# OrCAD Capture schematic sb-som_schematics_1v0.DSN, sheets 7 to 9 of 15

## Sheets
7 05. Parallel Display Interface: size C; title: SB-SOM    05. Parallel Display Interface
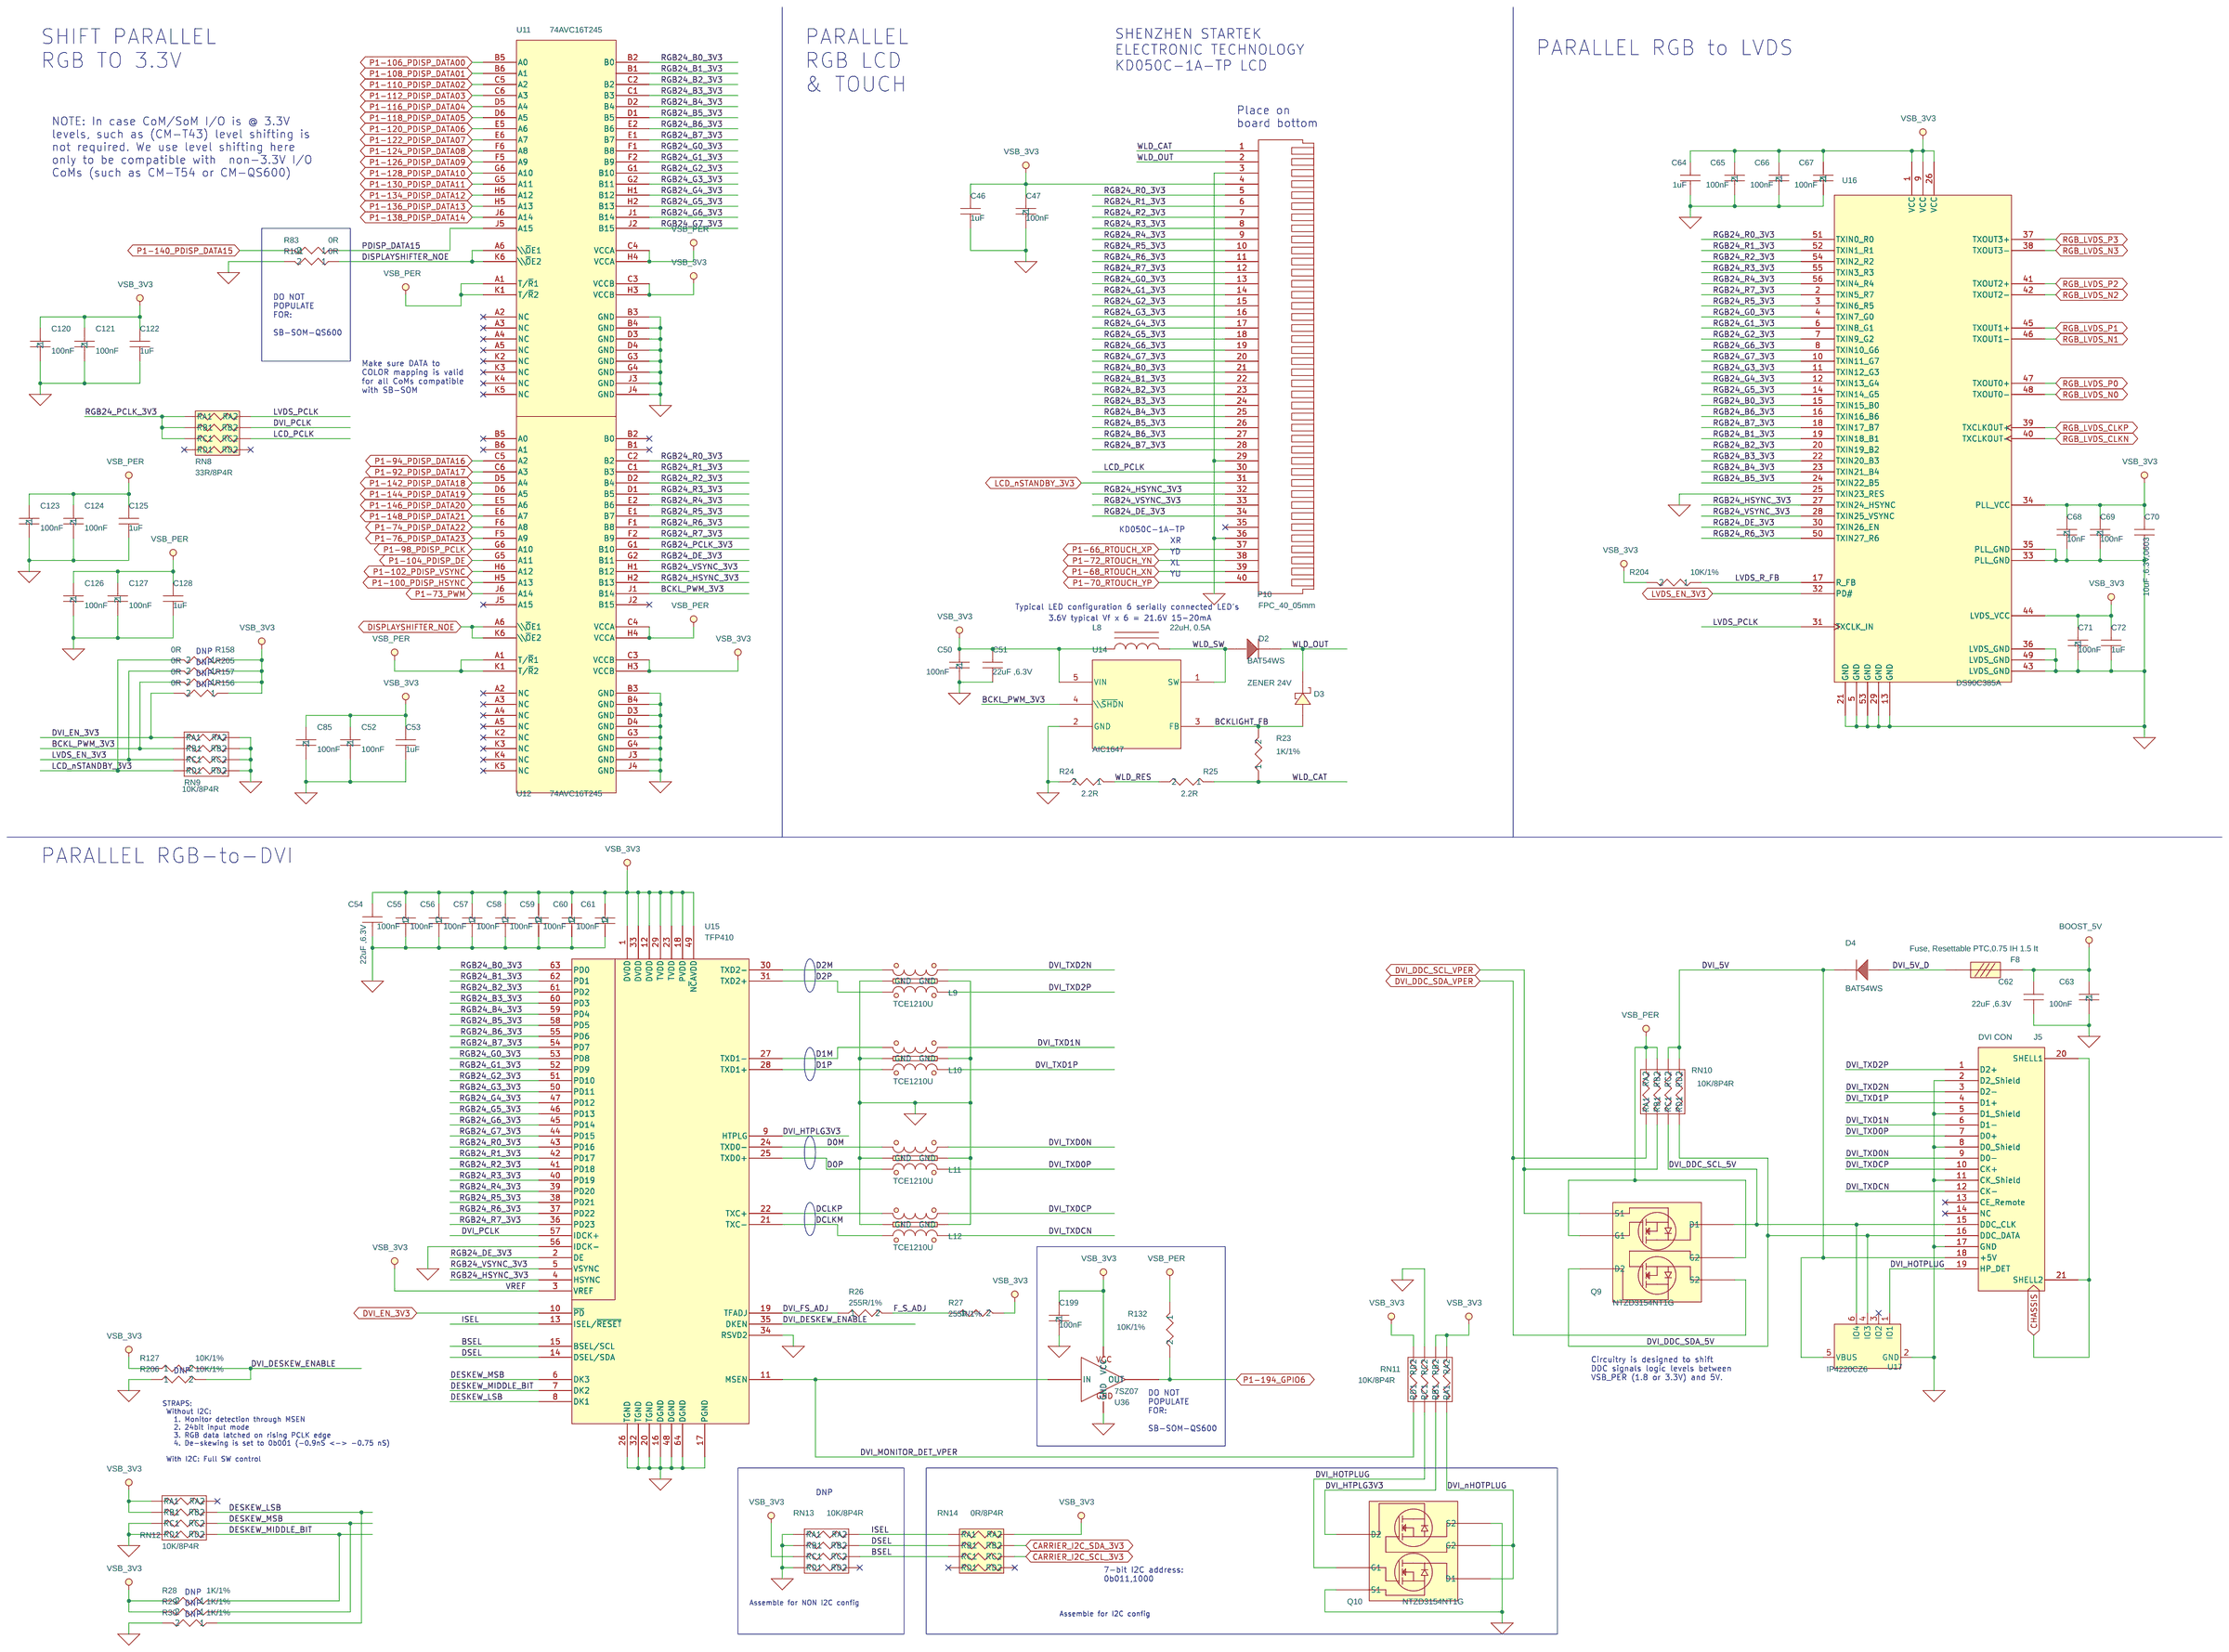
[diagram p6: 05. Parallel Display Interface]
8 07. PCIE & SATA: size C; title: SB-SOM    07. PCIE & SATA
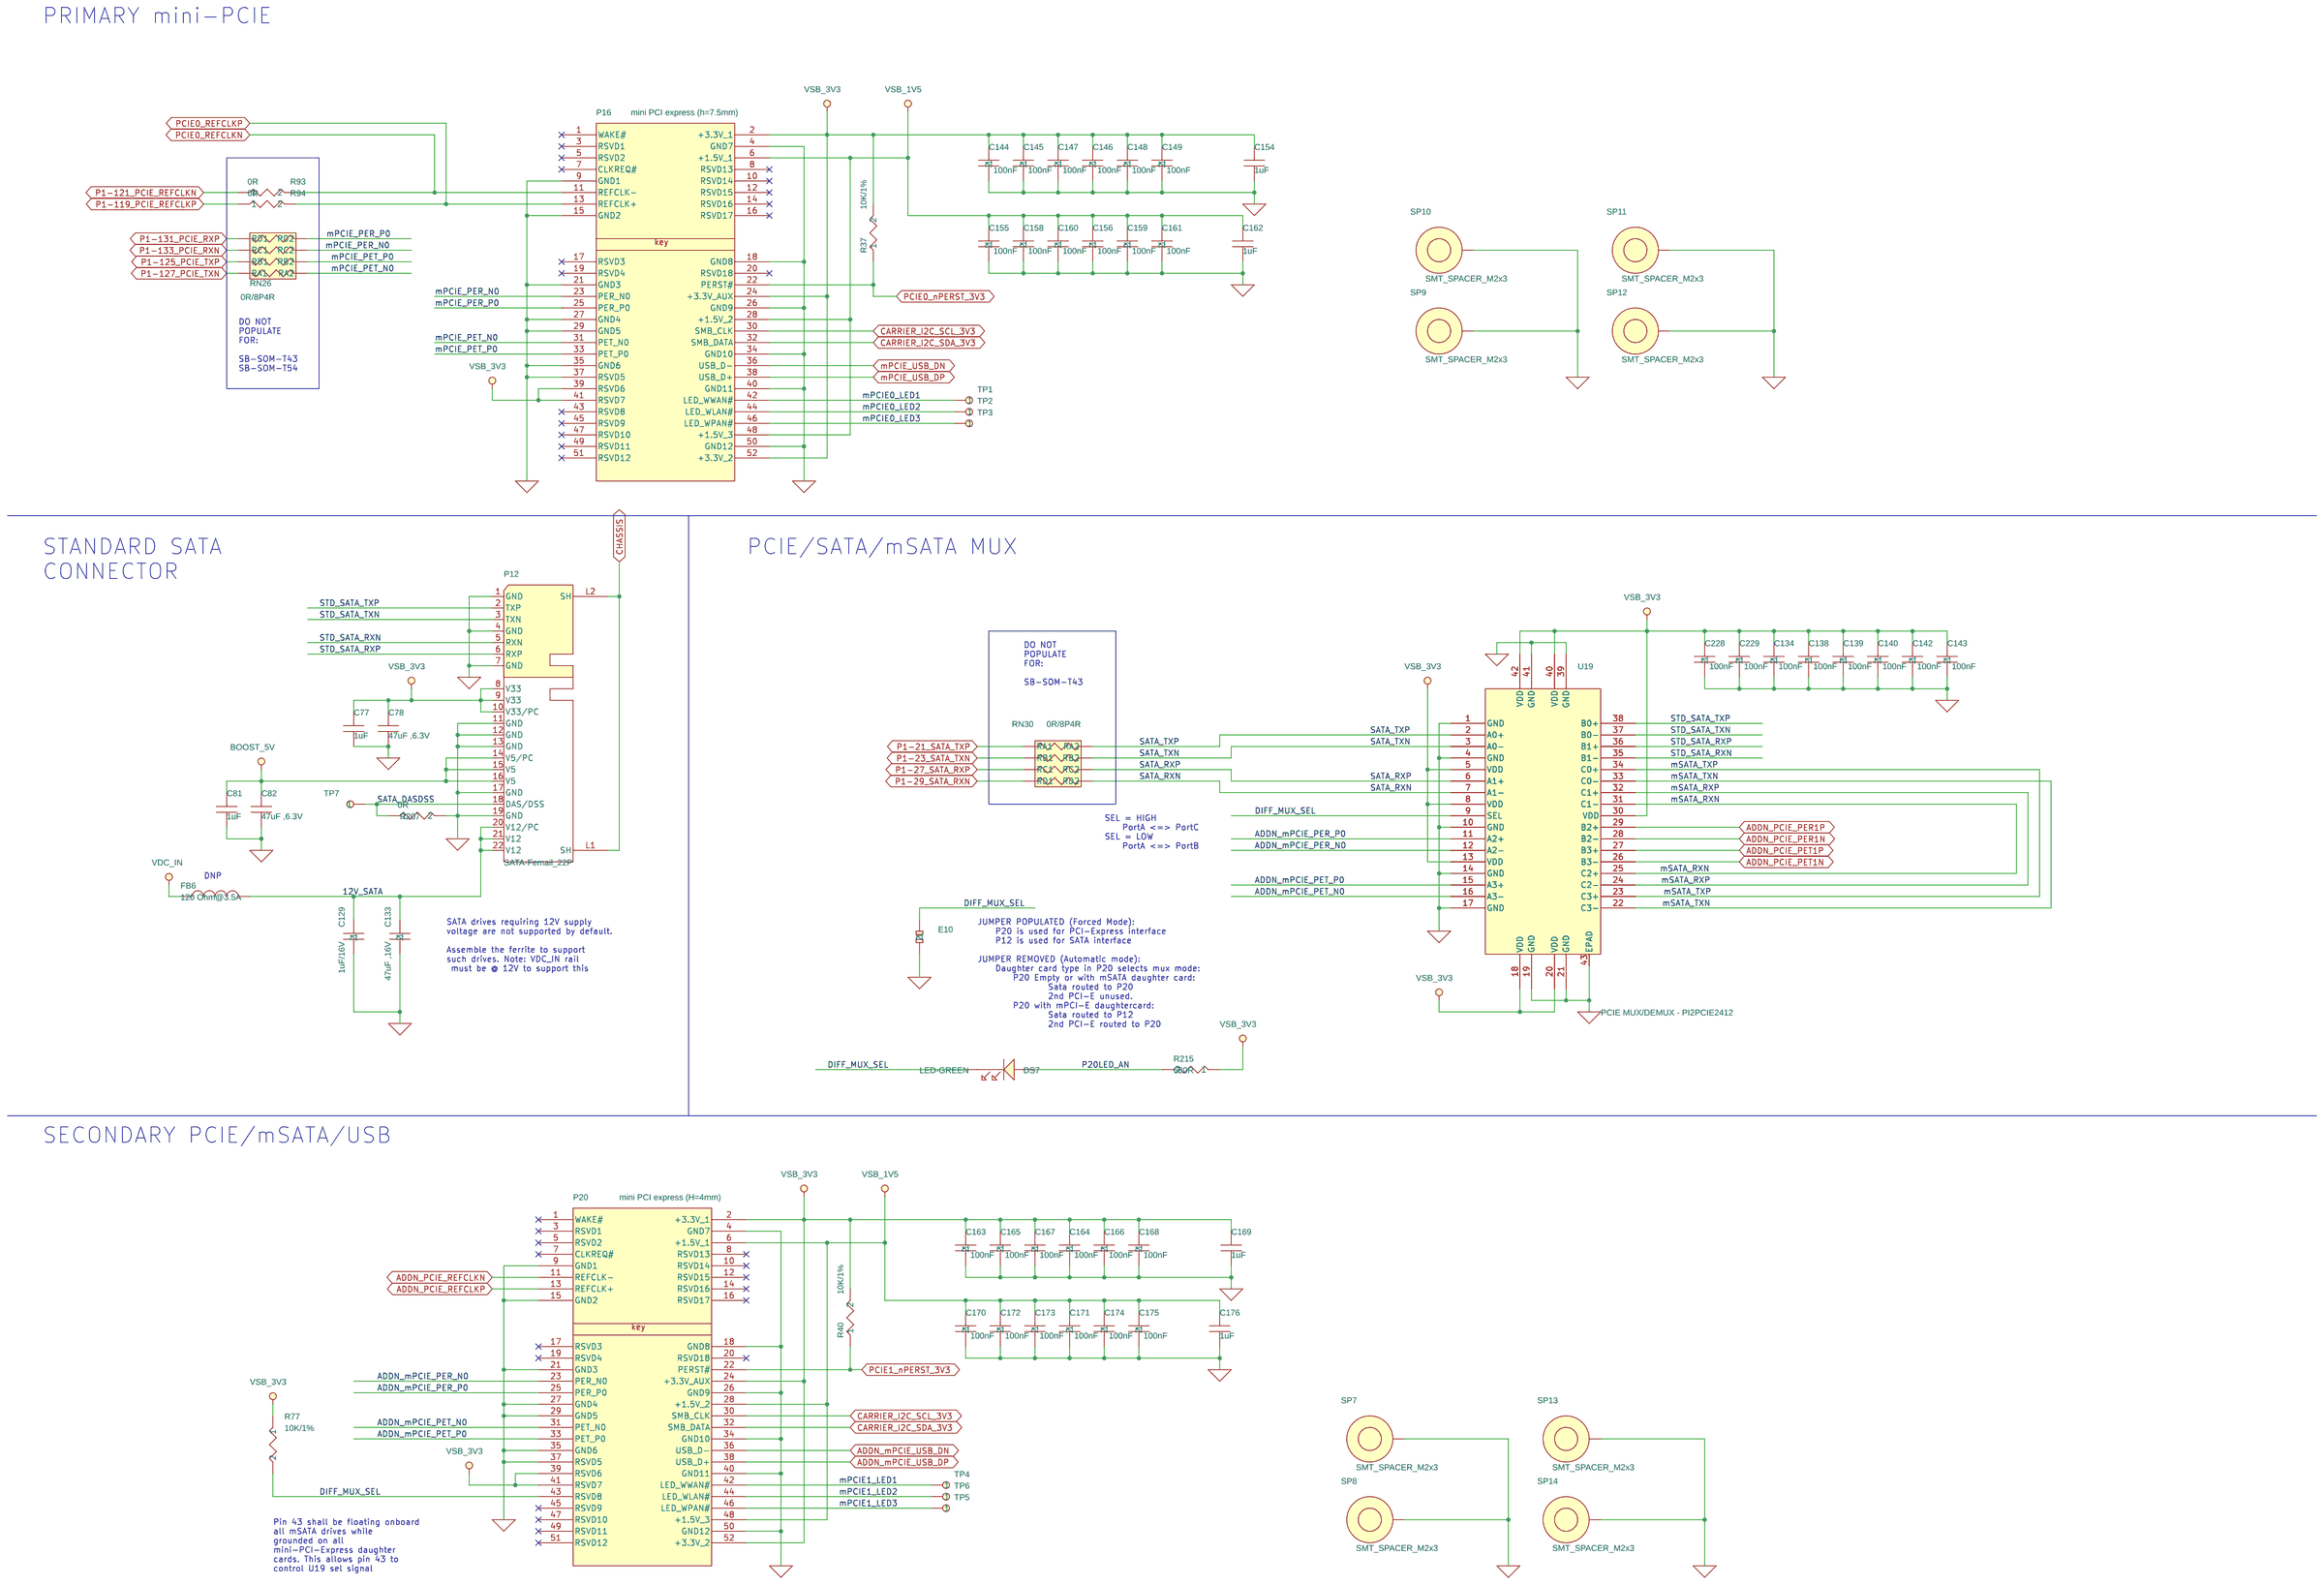
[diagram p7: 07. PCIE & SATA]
9 10. Power: size C; title: SB-SOM    10. Power
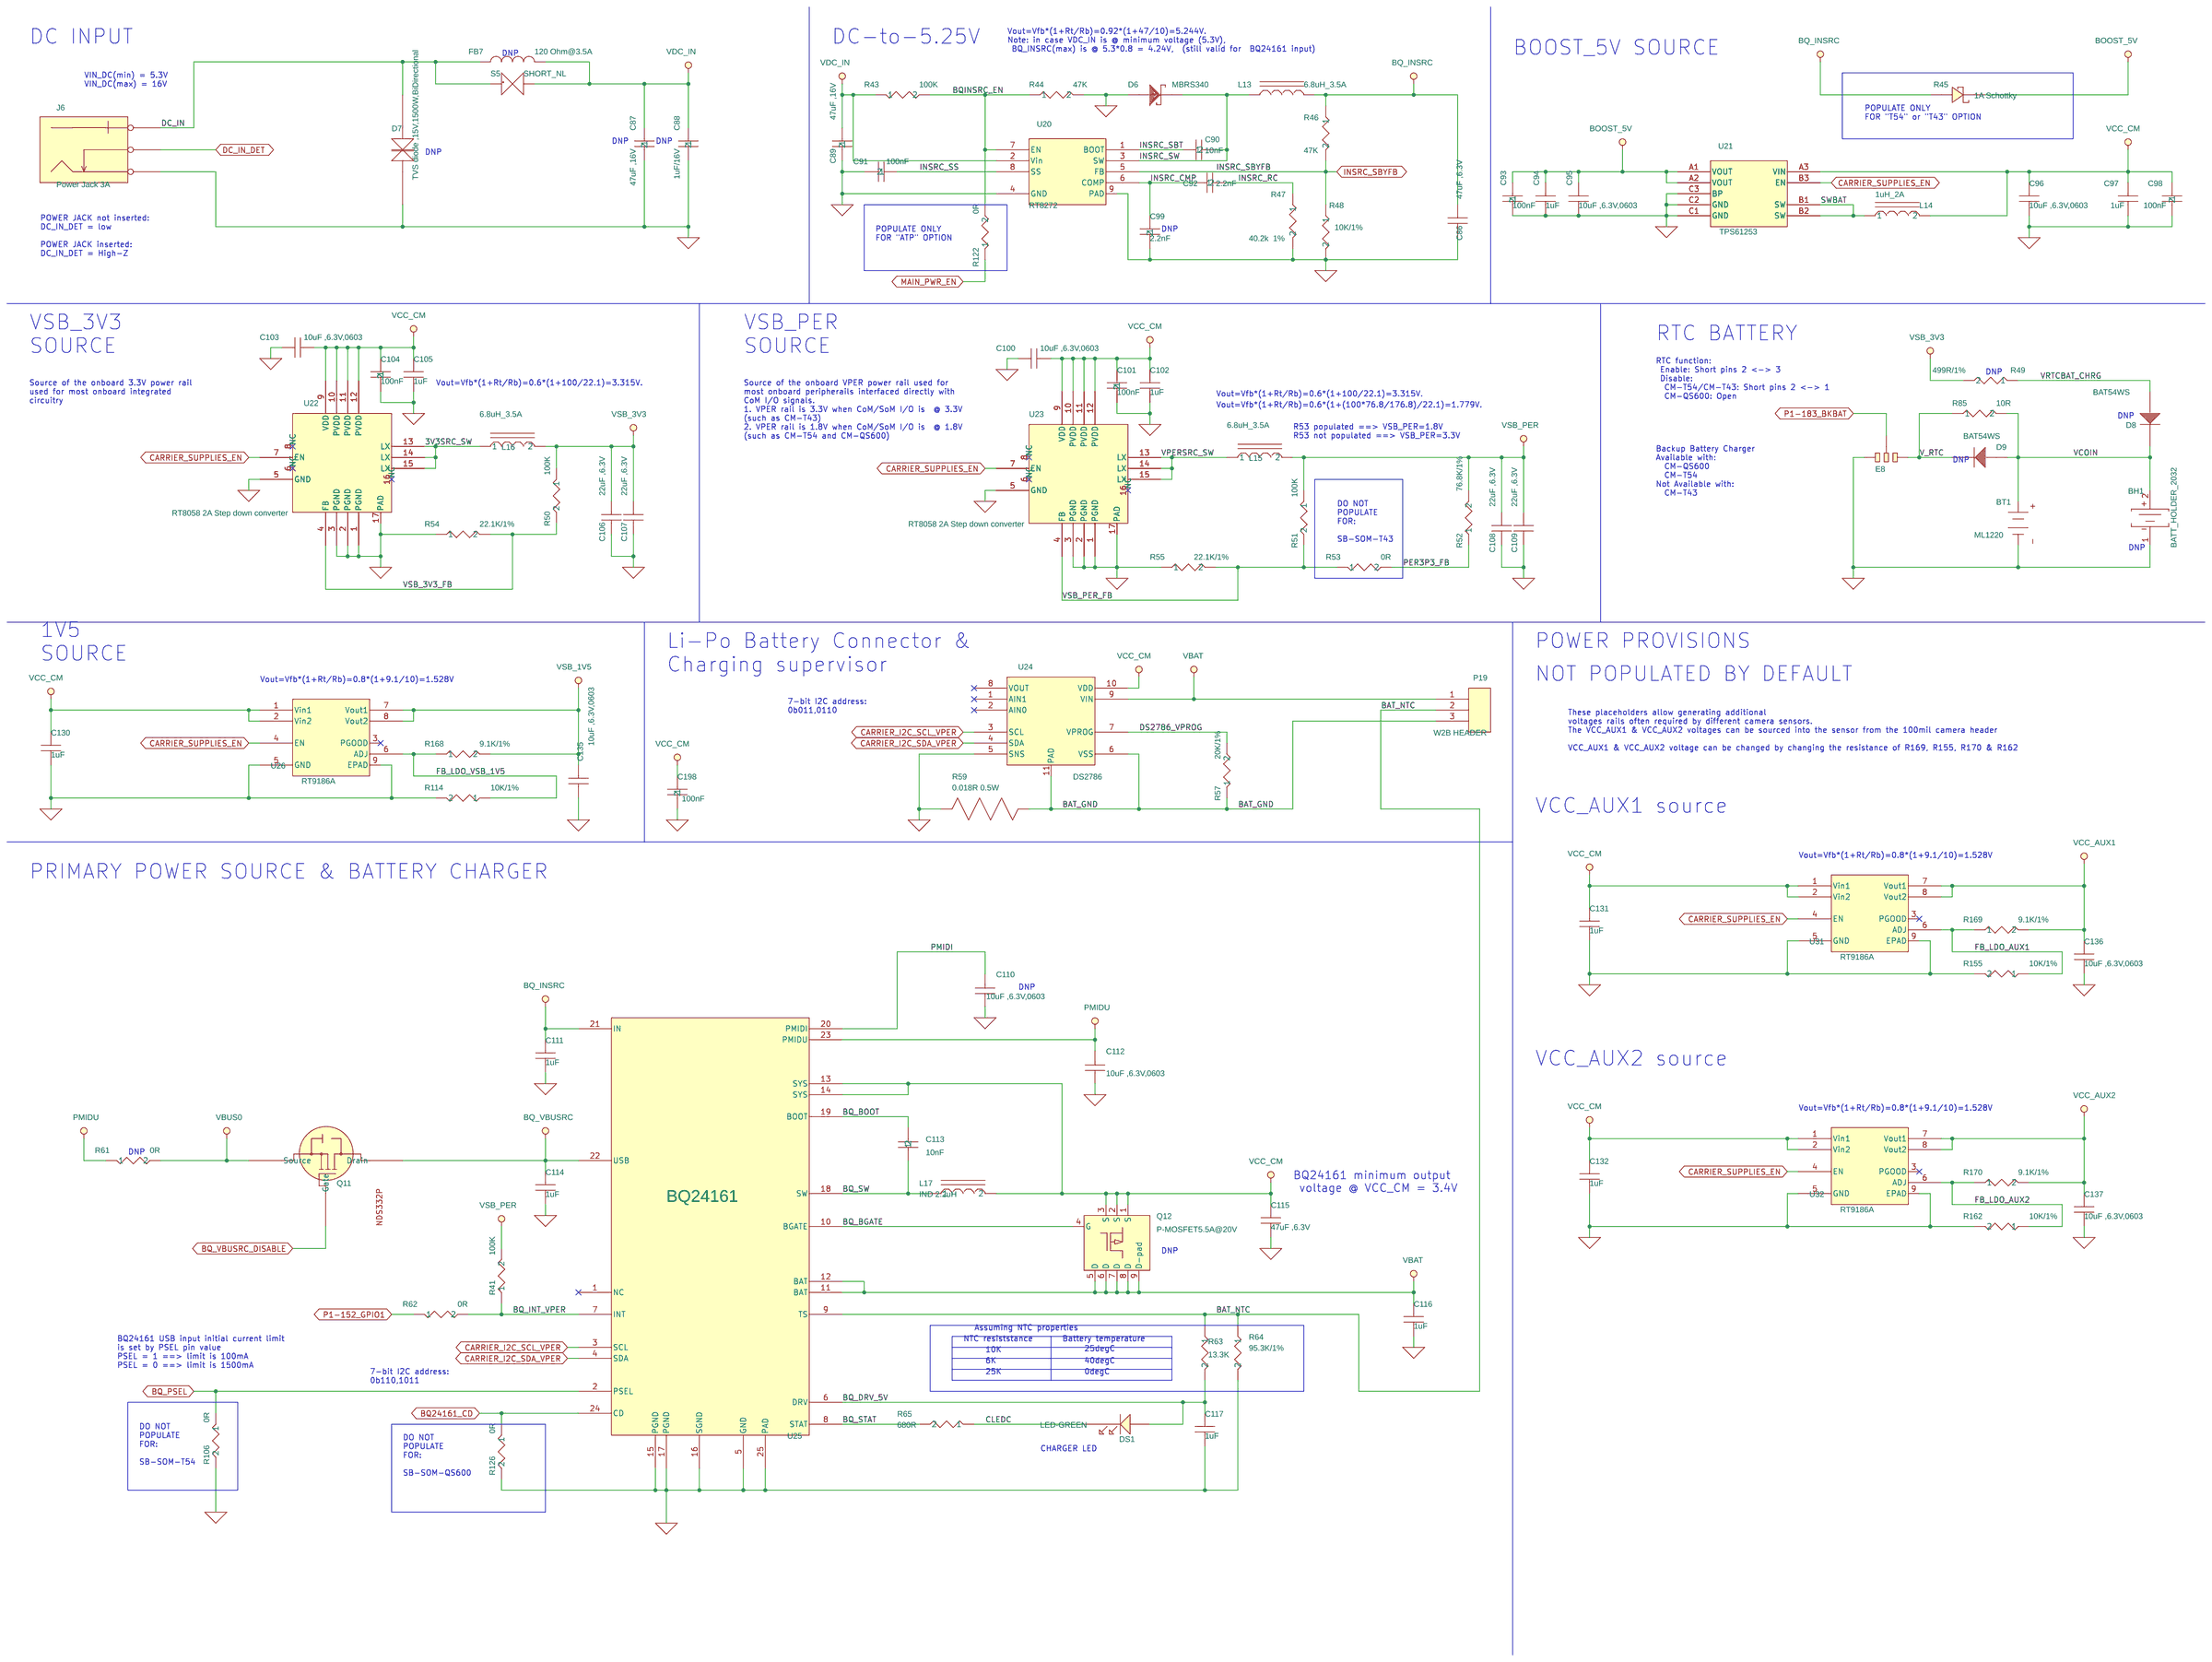
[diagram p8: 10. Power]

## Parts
sheet 05. Parallel Display Interface
C46  1uF  [RC0402]
C47  100nF  [RC0402]
C50  100nF  [RC0402]
C51  22uF ,6.3V  [RC0603]
C52  100nF  [RC0402]
C53  1uF  [RC0402]
C54  22uF ,6.3V  [RC0603]
C55  100nF  [RC0402]
C56  100nF  [RC0402]
C57  100nF  [RC0402]
C58  100nF  [RC0402]
C59  100nF  [RC0402]
C60  100nF  [RC0402]
C61  100nF  [RC0402]
C62  22uF ,6.3V  [RC0603]
C63  100nF  [RC0402]
C64  1uF  [RC0402]
C65  100nF  [RC0402]
C66  100nF  [RC0402]
C67  100nF  [RC0402]
C68  10nF  [RC0402]
C69  100nF  [RC0402]
C70  10uF ,6.3V,0603  [RC0603]
C71  100nF  [RC0402]
C72  1uF  [RC0402]
C85  100nF  [RC0402]
C120  100nF  [RC0402]
C121  100nF  [RC0402]
C122  1uF  [RC0402]
C123  100nF  [RC0402]
C124  100nF  [RC0402]
C125  1uF  [RC0402]
C126  100nF  [RC0402]
C127  100nF  [RC0402]
C128  1uF  [RC0402]
C199  100nF  [RC0402]
D2  BAT54WS  [SOD-323]
D3  ZENER 24V  [SOD-123]
D4  BAT54WS  [SOD-323]
F8  Fuse, Resettable PTC,0.75 IH 1.5 It  [FUSE-1206]
J5  DVI CON  [HDMI-A19-RASM]
L8  22uH, 0.5A  [IND4x4_5x3_2S]
L9  TCE1210U  [EMI1012-ESD]
L10  TCE1210U  [EMI1012-ESD]
L11  TCE1210U  [EMI1012-ESD]
L12  TCE1210U  [EMI1012-ESD]
P10  FPC_40_05mm  [FPC05SM40-1]
Q9  NTZD3154NT1G  [SOT-563]
Q10  NTZD3154NT1G  [SOT-563]
R23  1K/1%  [RC0402]
R24  2.2R  [RC0402]
R25  2.2R  [RC0402]
R26  255R/1%  [RC0402]
R27  255R/1%  [RC0402]
R28  1K/1%  [RC0402]
R29  1K/1%  [RC0402]
R30  1K/1%  [RC0402]
R83  0R  [RC0402]
R101  0R  [RC0402]
R127  10K/1%  [RC0402]
R132  10K/1%  [RC0402]
R156  0R  [RC0402]
R157  0R  [RC0402]
R158  0R  [RC0402]
R204  10K/1%  [RC0402]
R205  0R  [RC0402]
R206  10K/1%  [RC0402]
RN8  33R/8P4R  [RESNET8P0805]
RN9  10K/8P4R  [RESNET8P0805]
RN10  10K/8P4R  [RESNET8P0805]
RN11  10K/8P4R  [RESNET8P0805]
RN12  10K/8P4R  [RESNET8P0805]
RN13  10K/8P4R  [RESNET8P0805]
RN14  0R/8P4R  [RESNET8P0805]
U11  74AVC16T245  [BGA-56-065-7X4_5]
U12  74AVC16T245  [BGA-56-065-7X4_5]
U14  AIC1647  [SOT23-5]
U15  TFP410  [TQFP-64]
U16  DS90C385A  [TSSOP-56]
U17  IP4220CZ6  [SOT23-6L]
U36  7SZ07  [SC70]
sheet 07. PCIE & SATA
C77  1uF  [RC0402]
C78  47uF ,6.3V  [C0805]
C81  1uF  [RC0402]
C82  47uF ,6.3V  [C0805]
C129  1uF/16V  [RC0805]
C133  47uF ,16V  [C1210H2_5]
C134  100nF  [RC0402]
C138  100nF  [RC0402]
C139  100nF  [RC0402]
C140  100nF  [RC0402]
C142  100nF  [RC0402]
C143  100nF  [RC0402]
C144  100nF  [RC0402]
C145  100nF  [RC0402]
C146  100nF  [RC0402]
C147  100nF  [RC0402]
C148  100nF  [RC0402]
C149  100nF  [RC0402]
C154  1uF  [RC0402]
C155  100nF  [RC0402]
C156  100nF  [RC0402]
C158  100nF  [RC0402]
C159  100nF  [RC0402]
C160  100nF  [RC0402]
C161  100nF  [RC0402]
C162  1uF  [RC0402]
C163  100nF  [RC0402]
C164  100nF  [RC0402]
C165  100nF  [RC0402]
C166  100nF  [RC0402]
C167  100nF  [RC0402]
C168  100nF  [RC0402]
C169  1uF  [RC0402]
C170  100nF  [RC0402]
C171  100nF  [RC0402]
C172  100nF  [RC0402]
C173  100nF  [RC0402]
C174  100nF  [RC0402]
C175  100nF  [RC0402]
C176  1uF  [RC0402]
C228  100nF  [RC0402]
C229  100nF  [RC0402]
DS7  LED-GREEN  [LED-1206]
E10  HDR1X2  [1X2THHDR]
FB6  120 Ohm@3.5A  [1206]
P12  SATA-Femail_22P  [SATA-22-V-TH]
P16  mini PCI express (h=7.5mm)  [MINIPCIE-4]
P20  mini PCI express (H=4mm)  [MINIPCIE-4]
R37  10K/1%  [RC0402]
R40  10K/1%  [RC0402]
R77  10K/1%  [RC0402]
R93  0R  [RC0402]
R94  0R  [RC0402]
R207  0R  [RC0402]
R215  680R  [RC0402]
RN26  0R/8P4R  [RESNET8P0805]
RN30  0R/8P4R  [RESNET8P0805]
SP7  SMT_SPACER_M2x3  [MINIPCIE-4-Spacer]
SP8  SMT_SPACER_M2x3  [MINIPCIE-4-Spacer]
SP9  SMT_SPACER_M2x3  [MINIPCIE-4-Spacer]
SP10  SMT_SPACER_M2x3  [MINIPCIE-4-Spacer]
SP11  SMT_SPACER_M2x3  [MINIPCIE-4-Spacer]
SP12  SMT_SPACER_M2x3  [MINIPCIE-4-Spacer]
SP13  SMT_SPACER_M2x3  [MINIPCIE-4-Spacer]
SP14  SMT_SPACER_M2x3  [MINIPCIE-4-Spacer]
TP1  TESTPOINT  [TESTPOINT]
TP2  TESTPOINT  [TESTPOINT]
TP3  TESTPOINT  [TESTPOINT]
TP4  TESTPOINT  [TESTPOINT]
TP5  TESTPOINT  [TESTPOINT]
TP6  TESTPOINT  [TESTPOINT]
TP7  TESTPOINT  [TESTPOINT]
U19  PCIE MUX/DEMUX - PI2PCIE2412  [MO-220VMFD-2x7.5]
sheet 10. Power
BH1  BATT_HOLDER_2032  [BATTH20MM]
BT1  ML1220  [BT1220SM]
C86  47uF ,6.3V  [C0805]
C87  47uF ,16V  [C1210H2_5]
C88  1uF/16V  [RC0805]
C89  47uF ,16V  [C1210H2_5]
C90  10nF  [RC0402]
C91  100nF  [RC0402]
C92  2.2nF  [RC0402]
C93  100nF  [RC0402]
C94  1uF  [RC0402]
C95  10uF ,6.3V,0603  [RC0603]
C96  10uF ,6.3V,0603  [RC0603]
C97  1uF  [RC0402]
C98  100nF  [RC0402]
C99  2.2nF  [RC0402]
C100  10uF ,6.3V,0603  [RC0603]
C101  100nF  [RC0402]
C102  1uF  [RC0402]
C103  10uF ,6.3V,0603  [RC0603]
C104  100nF  [RC0402]
C105  1uF  [RC0402]
C106  22uF ,6.3V  [RC0603]
C107  22uF ,6.3V  [RC0603]
C108  22uF ,6.3V  [RC0603]
C109  22uF ,6.3V  [RC0603]
C110  10uF ,6.3V,0603  [RC0603]
C111  1uF  [RC0402]
C112  10uF ,6.3V,0603  [RC0603]
C113  10nF  [RC0402]
C114  1uF  [RC0402]
C115  47uF ,6.3V  [0805]
C116  1uF  [RC0402]
C117  1uF  [RC0402]
C130  1uF  [RC0402]
C131  1uF  [RC0402]
C132  1uF  [RC0402]
C135  10uF ,6.3V,0603  [C0603-08]
C136  10uF ,6.3V,0603  [C0603-08]
C137  10uF ,6.3V,0603  [C0603-08]
C198  100nF  [RC0402]
D6  MBRS340  [DO-214AB]
D7  TVS diode ,15V,1500W,BiDirectional  [DO-214AB]
D8  BAT54WS  [SOD-323]
D9  BAT54WS  [SOD-323]
DS1  LED-GREEN  [LED-1206]
E8  JP3  [1X3THHDR]
FB7  120 Ohm@3.5A  [1206]
J6  Power Jack 3A  [PJ-0210-TH]
L13  6.8uH_3.5A  [IND8_2x8_2]
L14  1uH_2A  [IND-3x3_5]
L15  6.8uH_3.5A  [IND8_2x8_2]
L16  6.8uH_3.5A  [IND8_2x8_2]
L17  IND 2.2uH  [IND4_3x4_7SM]
P19  W2B HEADER  [1x3W2B1_5RASM]
Q11  NDS332P
Q12  P-MOSFET5.5A@20V  [Powerpak1212-8]
R41  100K  [RC0402]
R43  100K  [RC0402]
R44  47K  [RC0402]
R45  1A Schottky  [SOD-123]
R46  47K  [RC0402]
R47  40.2k  1%  [RC0402]
R48  10K/1%  [RC0402]
R49  499R/1%  [RC0402]
R50  100K  [RC0402]
R51  100K  [RC0402]
R52  76.8K/1%  [RC0402]
R53  0R  [RC0402]
R54  22.1K/1%  [RC0402]
R55  22.1K/1%  [RC0402]
R57  20K/1%  [RC0402]
R59  0.018R 0.5W  [R2010]
R61  0R  [RC0402]
R62  0R  [RC0402]
R63  13.3K  [RC0402]
R64  95.3K/1%  [RC0402]
R65  680R  [RC0402]
R85  10R  [RC0402]
R106  0R  [RC0402]
R114  10K/1%  [RC0402]
R122  0R  [RC0402]
R126  0R  [RC0402]
R155  10K/1%  [RC0402]
R162  10K/1%  [RC0402]
R168  9.1K/1%  [RC0402]
R169  9.1K/1%  [RC0402]
R170  9.1K/1%  [RC0402]
S5  SHORT_NL  [JUMPER-VIA_1]
U20  RT8272  [PSOP-8-2X2]
U21  TPS61253  [BGA-9-04-1.4x1.3]
U22  RT8058 2A Step down converter  [WQFN-16L3x3]
U23  RT8058 2A Step down converter  [WQFN-16L3x3]
U24  DS2786  [DFN3x3-10]
U25  BQ24161  [MO-220VGGD-8]
U26  RT9186A  [DFN3x3-8]
U31  RT9186A  [DFN3x3-8]
U32  RT9186A  [DFN3x3-8]

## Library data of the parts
C46 C53 C64 C72 C122 C125 C128 C130 = 1uF,X5R,6.3V,0402: CLABCONF0: = SB-SOM
C47 = 100nF,_10V,_X7R,_10%,_0402_13: CLABCONF0: = SB-SOM
C50 C104 = 100nF,_10V,_X7R,_10%,_0402_3: CLABCONF0: = SB-SOM
C51 C109 = 22uF,6.3V,X5R_1: CLABCONF0: = SB-SOM; P/N: 151B22610S
C52 = 100nF,_10V,_X7R,_10%,_0402_18: CLABCONF0: = SB-SOM; Group: LAN2
C54 C107 = 22uF,6.3V,X5R: CLABCONF0: = SB-SOM; P/N: 151B22610S
C55 = 100nF,_10V,_X7R,_10%,_0402_15: CLABCONF0: = SB-SOM
C56 = 100nF,_10V,_X7R,_10%,_0402_11: CLABCONF0: = SB-SOM
C57 = 100nF,_10V,_X7R,_10%,_0402_8: CLABCONF0: = SB-SOM
C58 = 100nF,_10V,_X7R,_10%,_0402_7: CLABCONF0: = SB-SOM
C59 C93 = 100nF,_10V,_X7R,_10%,_0402_1: CLABCONF0: = SB-SOM
C60 C198 = 100nF,_10V,_X7R,_10%,_0402_2: CLABCONF0: = SB-SOM
C61 = 100nF,_10V,_X7R,_10%,_0402_21: CLABCONF0: = SB-SOM
C62 C106 = 22uF,6.3V,X5R_2: CLABCONF0: = SB-SOM; P/N: 151B22610S
C63 = 100nF,_10V,_X7R,_10%,_0402_4: CLABCONF0: = SB-SOM; Group: LAN2
C65 = 100nF,_10V,_X7R,_10%,_0402_19: CLABCONF0: = SB-SOM; Group: Always
C66 = 100nF,_10V,_X7R,_10%,_0402_16: CLABCONF0: = SB-SOM; Group: Always
C67 = 100nF,_10V,_X7R,_10%,_0402_22: CLABCONF0: = SB-SOM; Group: Always
C68 = 10nF,_25V,_X7R,_10%,_0402: CLABCONF0: = SB-SOM; Group: LVDS
C69 = 100nF,_10V,_X7R,_10%,_0402: CLABCONF0: = SB-SOM; Group: LVDS
C70 = 10uF,6.3V,0603,X5R: CLABCONF0: = SB-SOM
C71 = 100nF,_10V,_X7R,_10%,_0402_20: CLABCONF0: = SB-SOM; Group: Always
C85 = 100nF,_10V,_X7R,_10%,_0402_9: CLABCONF0: = SB-SOM; Group: LAN2
C120 = 100nF,_10V,_X7R,_10%,_0402_6: CLABCONF0: = SB-SOM; Group: LAN2
C121 = 100nF,_10V,_X7R,_10%,_0402_12: CLABCONF0: = SB-SOM; Group: LAN2
C123 = 100nF,_10V,_X7R,_10%,_0402_10: CLABCONF0: = SB-SOM; Group: LAN2
C124 = 100nF,_10V,_X7R,_10%,_0402_17: CLABCONF0: = SB-SOM; Group: LAN2
C126 = 100nF,_10V,_X7R,_10%,_0402_23: CLABCONF0: = SB-SOM; Group: LAN2
C127 = 100nF,_10V,_X7R,_10%,_0402_5: CLABCONF0: = SB-SOM; Group: LAN2
C199 = 100nF,_10V,_X7R,_10%,_0402_14: CLABCONF0: = SB-SOM AND NOT QS600
D2 D4 = BAT54WS_0: CLABCONF0: = SB-SOM
D3 = ZENER_24V_500mW_SOD-123: CLABCONF0: = SB-SOM
F8 = Fuse,_0.75A_Ih,_1.5A_It: CLABCONF0: = SB-SOM
J5 = HDMI_Connector: CLABCONF0: = SB-SOM
L8 = IND,47uH,220mA,IND1812_2: CLABCONF0: = SB-SOM; P/N: 147A22000S
L9-L12 = ESD_CHOKE_DIFFx2_10: CLABCONF0: = SB-SOM; P/N: 142D11801S
P10 = FPC_40_05mm: CLABCONF0: = SB-SOM; Group: Always
Q9 Q10 = MOSFET_N_DUAL_0_0.4A_20V: CLABCONF0: = SB-SOM
R23 = 1K,1%,0402,1_16W_1: CLABCONF0: = SB-SOM
R24 = 2.2R,5%,0402,1_16W: CLABCONF0: = SB-SOM
R25 = 2.2R,5%,0402,1_16W_1: CLABCONF0: = SB-SOM
R26 = 255R_1%,0402_1: CLABCONF0: = SB-SOM
R27 = 255R_1%,0402: CLABCONF0: = SB-SOM
R28 = 1K,1%,0402,1_16W_2: CLABCONF0: DNP
R29 = 1K,1%,0402,1_16W_3: CLABCONF0: DNP
R30 = 1K,1%,0402,1_16W: CLABCONF0: DNP
R83 = 0R,_0402_3: CLABCONF0: = SB-SOM AND NOT QS600
R62 R101 = 0R,_0402_2: CLABCONF0: = SB-SOM AND NOT QS600
R127 = 10K,1%,0402,1_16W_1: CLABCONF0: = SB-SOM
R132 = 10K,1%,0402,1_16W_2: CLABCONF0: = SB-SOM AND NOT QS600
R156 = 0R,_0402_4: CLABCONF0: DNP
R157 = 0R,_0402_5: CLABCONF0: DNP
R61 R158 = 0R,_0402: CLABCONF0: DNP
R204 = 10K,1%,0402,1_16W: CLABCONF0: = SB-SOM
R205 = 0R,_0402_1: CLABCONF0: DNP
R206 = 10K,1%,0402,1_16W_3: CLABCONF0: DNP
RN8 = RN,33R,8P4R@0805: CLABCONF0: = SB-SOM
RN9-RN12 = RN,10K,8P4R@0805: CLABCONF0: = SB-SOM
RN13 = RN,10K,8P4R@0805: CLABCONF0: DNP
RN14 = RN,0R,8P4R@0805: CLABCONF0: = SB-SOM
U11 U12 = 74AVC16T245: CLABCONF0: = SB-SOM; P/N: 106RV2451S
U14 = AIC1647: CLABCONF0: = SB-SOM
U15 = tfp513_0: CLABCONF0: = SB-SOM; P/N: 116A01640S
U16 = DS90C385A_5: CLABCONF0: = SB-SOM; P/N: 116A03651S
U17 = IP4220CZ6_0: CLABCONF0: = SB-SOM
U36 = 7SZ07D,_buffer: CLABCONF0: = SB-SOM AND NOT QS600; P/N: 106D20070S
C77 C81 C169 C176 = 1uF,X5R,6.3V,0402: CLABCONF0: = SB-SOM AND NOT T43
C78 = 47uF,6.3V,X5R_1: CLABCONF0: = SB-SOM AND NOT T43
C82 = 47uF,6.3V,X5R: CLABCONF0: = SB-SOM AND NOT T43
C88 C129 = 1uF,_16V,_X7R,_20%,_0805: CLABCONF0: DNP
C133 = Cap.,_47uF,_16V,_X5R: CLABCONF0: DNP
C134 = 100nF,_10V,_X7R,_10%,_0402_8: CLABCONF0: = SB-SOM AND NOT T43
C138 = 100nF,_10V,_X7R,_10%,_0402: CLABCONF0: = SB-SOM AND NOT T43
C139 = 100nF,_10V,_X7R,_10%,_0402_25: CLABCONF0: = SB-SOM AND NOT T43
C140 = 100nF,_10V,_X7R,_10%,_0402_17: CLABCONF0: = SB-SOM AND NOT T43
C142 = 100nF,_10V,_X7R,_10%,_0402_12: CLABCONF0: = SB-SOM AND NOT T43
C143 = 100nF,_10V,_X7R,_10%,_0402_2: CLABCONF0: = SB-SOM AND NOT T43
C144 = 100nF,_10V,_X7R,_10%,_0402_11: CLABCONF0: = SB-SOM AND NOT T54 AND NOT T43
C145 = 100nF,_10V,_X7R,_10%,_0402_26: CLABCONF0: = SB-SOM AND NOT T54 AND NOT T43
C146 = 100nF,_10V,_X7R,_10%,_0402_9: CLABCONF0: = SB-SOM AND NOT T54 AND NOT T43
C147 = 100nF,_10V,_X7R,_10%,_0402_23: CLABCONF0: = SB-SOM AND NOT T54 AND NOT T43
C148 = 100nF,_10V,_X7R,_10%,_0402_6: CLABCONF0: = SB-SOM AND NOT T54 AND NOT T43
C149 = 100nF,_10V,_X7R,_10%,_0402_22: CLABCONF0: = SB-SOM AND NOT T54 AND NOT T43
C154 C162 = 1uF,X5R,6.3V,0402: CLABCONF0: = SB-SOM AND NOT T54 AND NOT T43
C155 = 100nF,_10V,_X7R,_10%,_0402_18: CLABCONF0: = SB-SOM AND NOT T54 AND NOT T43
C156 = 100nF,_10V,_X7R,_10%,_0402_1: CLABCONF0: = SB-SOM AND NOT T54 AND NOT T43
C158 = 100nF,_10V,_X7R,_10%,_0402_16: CLABCONF0: = SB-SOM AND NOT T54 AND NOT T43
C159 = 100nF,_10V,_X7R,_10%,_0402_31: CLABCONF0: = SB-SOM AND NOT T54 AND NOT T43
C160 = 100nF,_10V,_X7R,_10%,_0402_15: CLABCONF0: = SB-SOM AND NOT T54 AND NOT T43
C161 = 100nF,_10V,_X7R,_10%,_0402_19: CLABCONF0: = SB-SOM AND NOT T54 AND NOT T43
C163 = 100nF,_10V,_X7R,_10%,_0402_30: CLABCONF0: = SB-SOM AND NOT T43
C164 = 100nF,_10V,_X7R,_10%,_0402_14: CLABCONF0: = SB-SOM AND NOT T43
C165 = 100nF,_10V,_X7R,_10%,_0402_28: CLABCONF0: = SB-SOM AND NOT T43
C166 = 100nF,_10V,_X7R,_10%,_0402_13: CLABCONF0: = SB-SOM AND NOT T43
C167 = 100nF,_10V,_X7R,_10%,_0402_27: CLABCONF0: = SB-SOM AND NOT T43
C168 = 100nF,_10V,_X7R,_10%,_0402_29: CLABCONF0: = SB-SOM AND NOT T43
C170 = 100nF,_10V,_X7R,_10%,_0402_5: CLABCONF0: = SB-SOM AND NOT T43
C171 = 100nF,_10V,_X7R,_10%,_0402_21: CLABCONF0: = SB-SOM AND NOT T43
C172 = 100nF,_10V,_X7R,_10%,_0402_3: CLABCONF0: = SB-SOM AND NOT T43
C173 = 100nF,_10V,_X7R,_10%,_0402_24: CLABCONF0: = SB-SOM AND NOT T43
C174 = 100nF,_10V,_X7R,_10%,_0402_7: CLABCONF0: = SB-SOM AND NOT T43
C175 = 100nF,_10V,_X7R,_10%,_0402_10: CLABCONF0: = SB-SOM AND NOT T43
C228 = 100nF,_10V,_X7R,_10%,_0402_4: CLABCONF0: = SB-SOM AND NOT T43
C229 = 100nF,_10V,_X7R,_10%,_0402_20: CLABCONF0: = SB-SOM AND NOT T43
DS7 = LED-GREEN_1206_3: CLABCONF0: = SB-SOM AND NOT T43
E10 = HDR_1x2_100MIL_TH_JUMPER: CLABCONF0: = SB-SOM AND NOT T43
FB6 FB7 = Ferrite_bead_,_120_Ohm@3A: CLABCONF0: DNP
P12 = Conn.,_SATA_-_Rec,_15+7,_Vert: CLABCONF0: = SB-SOM AND NOT T43; P/N: 180K02200S
P16 = mini_PCIe: CLABCONF0: = SB-SOM AND NOT T54 AND NOT T43; P/N: 182K05202S
P20 = mini_PCIe: CLABCONF0: = SB-SOM AND NOT T43; P/N: 182K05201S
R37 = 10K,1%,0402,1_16W_1: CLABCONF0: = SB-SOM AND NOT T54 AND NOT T43
R40 = 10K,1%,0402,1_16W: CLABCONF0: = SB-SOM AND NOT T43
R77 = 10K,1%,0402,1_16W_2: CLABCONF0: = SB-SOM AND NOT T43
R93 = 0R,_0402_1: CLABCONF0: = SB-SOM AND NOT T54 AND NOT T43
R94 = 0R,_0402: CLABCONF0: = SB-SOM AND NOT T54 AND NOT T43
R207 = 0R,_0402_2: CLABCONF0: = SB-SOM AND NOT T43
R215 = 47K,_0402: CLABCONF0: = SB-SOM AND NOT T43; P/N: 161C68001S
RN26 = RN,0R,8P4R@0805: CLABCONF0: = SB-SOM AND NOT T54 AND NOT T43
RN30 = RN,0R,8P4R@0805: CLABCONF0: = SB-SOM AND NOT T43
SP7-SP9 SP12-SP14 = SMT_SPACER_M2x3: CLABCONF0: DNP
SP10 = SMT_SPACER_M2x3: CLABCONF0: = SB-SOM AND NOT T43
SP11 = SMT_SPACER_M2x3: CLABCONF0: = SB-SOM AND NOT T54 AND NOT T43
TP1-TP7 = TESTPOINT: CLABCONF0: DNP
U19 = PCIE_Mux_Demux_2_1: CLABCONF0: = SB-SOM AND NOT T43; P/N: 116A24123S
BH1 = BATT_HOLDER_0: CLABCONF0: DNP
BT1 = ML1020: CLABCONF0: = SB-SOM
C86 = 47uF,6.3V,X5R: CLABCONF0: = SB-SOM
C87 = Cap.,_47uF,_16V,_X5R_1: CLABCONF0: DNP
C89 = Cap.,_47uF,_16V,_X5R: CLABCONF0: = SB-SOM
C90 = 10nF,_25V,_X7R,_10%,_0402: CLABCONF0: = SB-SOM
C91 = 100nF,_10V,_X7R,_10%,_0402: CLABCONF0: = SB-SOM
C92 = 2.2nF,_50V,_X7R,_10%,_0402_1: CLABCONF0: = SB-SOM
C94 C97 C102 C105 = Cap_1uF,X5R,6.3V,0402: CLABCONF0: = SB-SOM
C95 = 10uF,6.3V,0603,20%X5R: CLABCONF0: = SB-SOM
C96 = 10uF,6.3V,0603,20%X5R_3: CLABCONF0: = SB-SOM
C98 = 100nF,_10V,_X7R,_10%,_0402_5: CLABCONF0: = SB-SOM
C99 = 2.2nF,_50V,_X7R,_10%,_0402: CLABCONF0: DNP
C100 = 10uF,6.3V,0603,20%X5R_1: CLABCONF0: = SB-SOM
C101 = 100nF,_10V,_X7R,_10%,_0402_4: CLABCONF0: = SB-SOM
C103 = 10uF,6.3V,0603,20%X5R_2: CLABCONF0: = SB-SOM
C108 = 22uF,6.3V,X5R_3: CLABCONF0: = SB-SOM; P/N: 151B22610S
C110 = 10uF,6.3V,0603,X5R_1: CLABCONF0: DNP
C111 C114 C116 C117 = 1uF,X5R,6.3V,0402: CLABCONF0: = SB-SOM AND NOT QS600
C112 = 10uF,6.3V,0603,X5R: CLABCONF0: = SB-SOM AND NOT QS600
C113 = 10nF,_25V,_X7R,_10%,_0402_1: CLABCONF0: = SB-SOM AND NOT QS600
C115 = Cap.,47uF,6.3V,X5R: CLABCONF0: = SB-SOM AND NOT QS600
C131 C132 = 1uF,X5R,6.3V,0402: CLABCONF0: DNP
C135 = 10uF,6_0.3V,0603,20%X5R: CLABCONF0: = SB-SOM
C136 C137 = 10uF,6_0.3V,0603,20%X5R: CLABCONF0: DNP
D6 = Diode_,MBRS340_,3A_0: CLABCONF0: = SB-SOM
D7 = Diode_,TVS_,15V,1500W_0: CLABCONF0: DNP; P/N: 132D00150S
D8 D9 = BAT54WS_0: CLABCONF0: DNP
DS1 = LED-GREEN_1206_3: CLABCONF0: = SB-SOM AND NOT QS600
E8 = HDR_1x3_100MIL_TH_JUMPER: CLABCONF0: = SB-SOM
J6 = Conn._DC,_TH,_3A: CLABCONF0: = SB-SOM
L13 = IND_6.8uH_3.5A: CLABCONF0: = SB-SOM; P/N: 147A6R801S
L14 = IND_DELTA_MPL73-2R2_2.2uH_14A_1: CLABCONF0: = SB-SOM; Isat: 7; Linit: 3.3uH; P/N: 147A1R001S
L15 = Ind_SIL525-2R2-2.2uH_@_2.1A_1: CLABCONF0: = SB-SOM; Isat: 3.5A; Linit: 6.8uH; P/N: 147A6R801S
L16 = Ind_SIL525-2R2-2.2uH_@_2.1A: CLABCONF0: = SB-SOM; Isat: 3.5A; Linit: 6.8uH; P/N: 147A6R801S
L17 = IND_DELTA_MPL73-2R2_2.2uH_14A: CLABCONF0: = SB-SOM AND NOT QS600; Group: Always; Isat: 5A; P/N: 147A2R204S
P19 = TMP_142956: CLABCONF0: = SB-SOM
Q11 = NDS332P: CLABCONF0: = SB-SOM AND NOT QS600
Q12 = MOSFET_P,_5.5A_20V: CLABCONF0: DNP
R41 = 100K,_0402: CLABCONF0: = SB-SOM AND NOT QS600; P/N: 161C10031S
R43 = 100K,_0402_2: CLABCONF0: = SB-SOM; P/N: 161C10031S
R44 = 47K,_0402_1: CLABCONF0: = SB-SOM
R45 = 1A_Schottky_Barrier_Rectifier: CLABCONF0: = SB-SOM AND NOT QS600
R46 = 47K,_0402_2: CLABCONF0: = SB-SOM
R47 = 40.2k_,1%: CLABCONF0: = SB-SOM
R48 = 10K,1%,0402,1_16W_2: CLABCONF0: = SB-SOM
R49 = 75R,1%,0402,1_16W: CLABCONF0: DNP; Group: POWER_48; P/N: 161C49901S
R50 = 100K,_0402_3: CLABCONF0: = SB-SOM; P/N: 161C10031S
R51 = 100K,_0402_1: CLABCONF0: = SB-SOM; P/N: 161C10031S
R52 = 76.8K_1%,_0402: CLABCONF0: = SB-SOM
R53 = 0R,_0402_3: CLABCONF0: = SB-SOM AND NOT T43
R54 = 22.1K_1%,_0402: CLABCONF0: = SB-SOM
R55 = 22.1K_1%,_0402_1: CLABCONF0: = SB-SOM
R57 = 20K_1%,_0402: CLABCONF0: = ATP; Group: AUD
R59 = 0.005R,2W,RCS1458: CLABCONF0: = SB-SOM; P/N: 161HR0181S
R63 = 13.3K,_0402_tmp: CLABCONF0: = SB-SOM AND NOT QS600; P/N: 161C13321S
R64 = 4.99K,1%,0402,1_16W: CLABCONF0: = SB-SOM AND NOT QS600; P/N: 161C95321S
R65 = 47K,_0402: CLABCONF0: = SB-SOM AND NOT QS600; P/N: 161C68001S
R85 = 10R,_0402: CLABCONF0: = SB-SOM
R106 = 0R,_0402_4: CLABCONF0: = SB-SOM AND NOT QS600 AND NOT T54
R114 = 10K,1%,0402,1_16W_3: CLABCONF0: = SB-SOM
R122 = 0R,_0402_1: CLABCONF0: = ATP
R126 = 0R,_0402_5: CLABCONF0: = SB-SOM AND NOT QS600
R155 = 10K,1%,0402,1_16W_1: CLABCONF0: DNP
R162 = 10K,1%,0402,1_16W: CLABCONF0: DNP
R168 = 953R,1%,0402,1_16W_0_2: CLABCONF0: = SB-SOM; P/N: 161C91011S
R169 = 953R,1%,0402,1_16W_0_1: CLABCONF0: DNP; P/N: 161C91011S
R170 = 953R,1%,0402,1_16W_0: CLABCONF0: DNP; P/N: 161C91011S
S5 = MISC_SHORT_NL: CLABCONF0: DNP
U20 = RT8272,Converter,3A,24V: CLABCONF0: = SB-SOM
U21 = TPS61253: CLABCONF0: = SB-SOM; P/N: 123C15200S
U22 U23 = RT8058_,Switcher_,2A: CLABCONF0: = SB-SOM
U24 = DS2786_,Fuel_Gauge: CLABCONF0: = SB-SOM
U25 = ISL9011_DUAL_LDO_11: CLABCONF0: = SB-SOM AND NOT QS600; P/N: 123D4R202S
U26 = RT9186A,LDO_,2.5-5_0.5V,500mA: CLABCONF0: = SB-SOM
U31 U32 = RT9186A,LDO_,2.5-5_0.5V,500mA: CLABCONF0: DNP

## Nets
3V3SRC_SW: L16.1 U22.13(LX) U22.14(LX) U22.15(LX)
12V_SATA: C129.1 C133.1 FB6.1 P12.20(V12/PC) P12.21(V12) P12.22(V12)
GND: BH1.1(MINUS) BT1.2(NEG) C46.2 C47.2 C50.2 C51.2 C52.2 C53.2 C54.2 C55.1 C56.1 C57.1 C58.1 C59.1 C60.1 C61.1 C62.2 C63.2 C64.2 C65.2 C66.2 C67.2 C68.2 C69.2 C70.2 C71.2 C72.2 C77.2 C78.2 C81.2 C82.2 C85.2 C86.2 C87.2 C88.2 C89.2 C91.2 C93.2 C94.2 C95.2 C96.2 C97.2 C98.2 C99.2 C100.1 C101.2 C102.2 C103.1 C104.2 C105.2 C106.2 C107.2 C108.2 C109.2 C110.1 C111.2 C112.1 C114.2 C115.2 C116.2 C117.2 C120.2 C121.2 C122.2 C123.2 C124.2 C125.2 C126.2 C127.2 C128.2 C129.2 C130.2 C131.2 C132.2 C133.2 C134.2 C135.2 C136.2 C137.2 C138.2 C139.2 C140.2 C142.2 C143.2 C144.2 C145.2 C146.2 C147.2 C148.2 C149.2 C154.2 C155.2 C156.2 C158.2 C159.2 C160.2 C161.2 C162.2 C163.2 C164.2 C165.2 C166.2 C167.2 C168.2 C169.2 C170.2 C171.2 C172.2 C173.2 C174.2 C175.2 C176.2 C198.2 C199.2 C228.2 C229.2 D6.ANODE D7.ANODE E8.1 E10.2 J5.2(D2_Shield) J5.5(D1_Shield) J5.8(D0_Shield) J5.11(CK_Shield) J5.17(GND) J6.3 L9.5(GND) L9.6(GND) L10.5(GND) L10.6(GND) L11.5(GND) L11.6(GND) L12.5(GND) L12.6(GND) P10.3 P10.29 P10.36 P12.1(GND) P12.4(GND) P12.7(GND) P12.11(GND) P12.12(GND) P12.13(GND) P12.17(GND) P12.19(GND) P16.4(GND7) P16.9(GND1) P16.15(GND2) P16.18(GND8) P16.21(GND3) P16.26(GND9) P16.27(GND4) P16.29(GND5) P16.34(GND10) P16.35(GND6) P16.37(RSVD5) P16.40(GND11) P16.50(GND12) P20.4(GND7) P20.9(GND1) P20.15(GND2) P20.18(GND8) P20.21(GND3) P20.26(GND9) P20.27(GND4) P20.29(GND5) P20.34(GND10) P20.35(GND6) P20.37(RSVD5) P20.40(GND11) P20.50(GND12) Q10.1(S1) Q10.4(S2) R24.2 R30.2 R44.2 R47.2 R48.2 R54.1 R55.1 R59.1 R64.2 R101.2 R106.2 R114.2 R126.2 R155.2 R162.2 R206.1 R207.2 RN9.5(RD2) RN9.6(RC2) RN9.7(RB2) RN9.8(RA2) RN11.6(RC2) RN12.3(RC1) RN12.4(RD1) RN13.1(RA1) RN13.2(RB1) RN13.4(RD1) SP7.1 SP8.1 SP9.1 SP10.1 SP11.1 SP12.1 SP13.1 SP14.1 U11.B3(GND) U11.B4(GND) U11.D3(GND) U11.D4(GND) U11.G3(GND) U11.G4(GND) U11.J3(GND) U11.J4(GND) U12.B3(GND) U12.B4(GND) U12.D3(GND) U12.D4(GND) U12.G3(GND) U12.G4(GND) U12.J3(GND) U12.J4(GND) U14.2(GND) U15.16(DGND) U15.17(PGND) U15.20(TGND) U15.26(TGND) U15.32(TGND) U15.34(RSVD2) U15.48(DGND) U15.56(IDCK-) U15.64(DGND) U16.5(GND) U16.13(GND) U16.21(GND) U16.25(TXIN23_RES) U16.29(GND) U16.33(PLL_GND) U16.35(PLL_GND) U16.36(LVDS_GND) U16.43(LVDS_GND) U16.49(LVDS_GND) U16.53(GND) U17.2(GND) U19.1(GND) U19.4(GND) U19.10(GND) U19.14(GND) U19.17(GND) U19.19(GND) U19.21(GND) U19.39(GND) U19.41(GND) U19.43(EPAD) U20.4(GND) U20.9(PAD) U21.C1(GND) U21.C2(GND) U21.C3(BP) U22.1(PGND) U22.2(PGND) U22.3(PGND) U22.5(GND) U22.17(PAD) U23.1(PGND) U23.2(PGND) U23.3(PGND) U23.5(GND) U23.17(PAD) U24.5(SNS) U25.5(GND) U25.15(PGND) U25.16(SGND) U25.17(PGND) U25.25(PAD) U26.5(GND) U26.9(EPAD) U31.5(GND) U31.9(EPAD) U32.5(GND) U32.9(EPAD) U36.3(GND) ; also on sheet 1 3 5 6 10 11 12 13 14
VBAT: C116.1 P19.1 Q12.5(D) Q12.6(D) Q12.7(D) Q12.8(D) Q12.9(D-pad) U24.9(VIN) U25.11(BAT) U25.12(BAT) ; also on sheet 14
VBUS0: Q11.2(Source) R61.2 ; also on sheet 5 10 11 13 14
VCC_AUX1: C136.1 R169.2 U31.7(Vout1) U31.8(Vout2) ; also on sheet 1
VCC_AUX2: C137.1 R170.2 U32.7(Vout1) U32.8(Vout2) ; also on sheet 1
VCC_CM: C96.1 C97.1 C98.1 C100.2 C101.1 C102.1 C103.2 C104.1 C105.1 C115.1 C130.1 C131.1 C132.1 C198.1 L14.2 L17.2 Q12.1(S) Q12.2(S) Q12.3(S) U21.A3(VIN) U22.9(VDD) U22.10(PVDD) U22.11(PVDD) U22.12(PVDD) U23.9(VDD) U23.10(PVDD) U23.11(PVDD) U23.12(PVDD) U24.10(VDD) U25.13(SYS) U25.14(SYS) U26.1(Vin1) U26.2(Vin2) U31.1(Vin1) U31.2(Vin2) U32.1(Vin1) U32.2(Vin2) ; also on sheet 6 10 12 14
ADDN_mPCIE_PER_N0: P20.23(PER_N0) U19.12(A2-)
ADDN_mPCIE_PER_P0: P20.25(PER_P0) U19.11(A2+)
ADDN_mPCIE_PET_N0: P20.31(PET_N0) U19.16(A3-)
ADDN_mPCIE_PET_P0: P20.33(PET_P0) U19.15(A3+)
ADDN_mPCIE_USB_DN: P20.36(USB_D-) ; also on sheet 5
ADDN_mPCIE_USB_DP: P20.38(USB_D+) ; also on sheet 5
ADDN_PCIE_PER1N: U19.28(B2-) ; also on sheet 12
ADDN_PCIE_PER1P: U19.29(B2+) ; also on sheet 12
ADDN_PCIE_PET1N: U19.26(B3-) ; also on sheet 12
ADDN_PCIE_PET1P: U19.27(B3+) ; also on sheet 12
ADDN_PCIE_REFCLKN: P20.11(REFCLK-) ; also on sheet 12
ADDN_PCIE_REFCLKP: P20.13(REFCLK+) ; also on sheet 12
BAT_GND: P19.3 R57.1 R59.2 U24.6(VSS) U24.11(PAD)
BAT_NTC: P19.2 R63.1 R64.1 U25.9(TS)
BCKL_PWM_3V3: R157.2 RN9.2(RB1) U12.J1(B14) U14.4(\\~{SHD}N)
BCKLIGHT_FB: D3.2(ANODE) R23.2 U14.3(FB)
BOOST_5V: C62.1 C63.1 C81.1 C82.1 C93.1 C94.1 C95.1 F8.2 P12.14(V5/PC) P12.15(V5) P12.16(V5) R45.1(CATHODE) U21.A1(VOUT) U21.A2(VOUT) ; also on sheet 1 3 5
BQ24161_CD: R126.1 U25.24(CD) ; also on sheet 14
BQ_BGATE: Q12.4(G) U25.10(BGATE)
BQ_BOOT: C113.2 U25.19(BOOT)
BQ_DRV_5V: C117.1 DS1.ANODE R63.2 U25.6(DRV)
BQ_INSRC: C86.1 C111.1 L13.2 R45.2(ANODE) R46.1 U25.21(IN) ; also on sheet 11 13 14
BQ_INT_VPER: R41.1 R62.2 U25.7(INT)
BQ_PSEL: R106.1 U25.2(PSEL) ; also on sheet 11
BQ_STAT: R65.2 U25.8(STAT)
BQ_SW: C113.1 L17.1 U25.18(SW)
BQ_VBUSRC: C114.1 Q11.3(Drain) U25.22(USB)
BQ_VBUSRC_DISABLE: Q11.1(Gate) ; also on sheet 11 13 14
BQINSRC_EN: R43.2 R44.1 R122.2 U20.7(EN)
BSEL: RN13.6(RC2) RN14.3(RC1) U15.15(BSEL/SCL)
CARRIER_I2C_SCL_3V3: P16.30(SMB_CLK) P20.30(SMB_CLK) RN14.6(RC2) ; also on sheet 3 6 12
CARRIER_I2C_SCL_VPER: U24.3(SCL) U25.3(SCL) ; also on sheet 1 6 11 13 14
CARRIER_I2C_SDA_3V3: P16.32(SMB_DATA) P20.32(SMB_DATA) RN14.7(RB2) ; also on sheet 3 6 12
CARRIER_I2C_SDA_VPER: U24.4(SDA) U25.4(SDA) ; also on sheet 1 6 11 13 14
CARRIER_SUPPLIES_EN: U21.B3(EN) U22.7(EN) U23.7(EN) U26.4(EN) U31.4(EN) U32.4(EN) ; also on sheet 12
CHASSIS: J5.20(SHELL1) J5.21(SHELL2) P12.L1(SH) P12.L2(SH) ; also on sheet 1 3 5 6 10
CLEDC: DS1.CATHODE R65.1
D0M: L11.3 U15.24(TXD0-)
D0P: L11.4 U15.25(TXD0+)
D1M: L10.3 U15.27(TXD1-)
D1P: L10.4 U15.28(TXD1+)
D2M: L9.3 U15.30(TXD2-)
D2P: L9.4 U15.31(TXD2+)
DC_IN: D7.CATHODE FB7.1 J6.1 S5.1
DC_IN_DET: J6.2 ; also on sheet 11 13
DCLKM: L12.3 U15.21(TXC-)
DCLKP: L12.4 U15.22(TXC+)
DESKEW_LSB: R30.1 RN12.7(RB2) U15.8(DK1)
DESKEW_MIDDLE_BIT: R28.1 RN12.5(RD2) U15.7(DK2)
DESKEW_MSB: R29.1 RN12.6(RC2) U15.6(DK3)
DIFF_MUX_SEL: DS7.CATHODE E10.1 P20.43(RSVD8) R77.2 U19.9(SEL)
DISPLAYSHIFTER_NOE: R101.1 U11.A6(\\~{O}E1) U11.K6(\\~{O}E2) U12.A6(\\~{O}E1) U12.K6(\\~{O}E2) ; also on sheet 14
DS2786_VPROG: R57.2 U24.7(VPROG)
DSEL: RN13.7(RB2) RN14.2(RB1) U15.14(DSEL/SDA)
DVI_5V: D4.CATHODE J5.18(+5V) RN10.5(RD2) RN10.6(RC2) U17.5(VBUS)
DVI_5V_D: D4.ANODE F8.1
DVI_DDC_SCL_5V: J5.15(DDC_CLK) Q9.6(D1) RN10.3(RC1) U17.6(IO4)
DVI_DDC_SCL_VPER: Q9.1(S1) RN10.2(RB1) ; also on sheet 11 13
DVI_DDC_SDA_5V: J5.16(DDC_DATA) Q9.3(D2) RN10.4(RD1) U17.4(IO3)
DVI_DDC_SDA_VPER: Q9.4(S2) RN10.1(RA1) ; also on sheet 11 13
DVI_DESKEW_ENABLE: R127.2 R206.2 U15.35(DKEN)
DVI_EN_3V3: R156.2 RN9.1(RA1) U15.10(~{PD}) ; also on sheet 6
DVI_FS_ADJ: R26.1 U15.19(TFADJ)
DVI_HOTPLUG: J5.19(HP_DET) Q10.2(G1) RN11.3(RC1) U17.1(IO1)
DVI_HTPLG3V3: Q10.3(D2) RN11.2(RB1) U15.9(HTPLG)
DVI_MONITOR_DET_VPER: RN11.4(RD1) U15.11(MSEN) U36.2(IN)
DVI_nHOTPLUG: Q10.5(G2) Q10.6(D1) RN11.1(RA1)
DVI_PCLK: RN8.7(RB2) U15.57(IDCK+)
DVI_TXD0N: J5.9(D0-) L11.2
DVI_TXD0P: J5.7(D0+) L11.1
DVI_TXD1N: J5.6(D1-) L10.2
DVI_TXD1P: J5.4(D1+) L10.1
DVI_TXD2N: J5.3(D2-) L9.2
DVI_TXD2P: J5.1(D2+) L9.1
DVI_TXDCN: J5.12(CK-) L12.2
DVI_TXDCP: J5.10(CK+) L12.1
F_S_ADJ: R26.2 R27.1
FB_LDO_AUX1: R155.1 R169.1 U31.6(ADJ)
FB_LDO_AUX2: R162.1 R170.1 U32.6(ADJ)
FB_LDO_VSB_1V5: R114.1 R168.1 U26.6(ADJ)
INSRC_CMP: C92.1 C99.1 U20.6(COMP)
INSRC_RC: C92.2 R47.1
INSRC_SBT: C90.1 U20.1(BOOT)
INSRC_SBYFB: R46.2 R48.1 U20.5(FB) ; also on sheet 14
INSRC_SS: C91.1 U20.8(SS)
INSRC_SW: C90.2 D6.CATHODE L13.1 U20.3(SW)
ISEL: RN13.8(RA2) RN14.1(RA1) U15.13(ISEL/~{RESET})
LCD_nSTANDBY_3V3: P10.31 R158.2 RN9.4(RD1) ; also on sheet 6
LCD_PCLK: P10.30 RN8.6(RC2)
LVDS_EN_3V3: R205.2 RN9.3(RC1) U16.32(PD#) ; also on sheet 6
LVDS_PCLK: RN8.8(RA2) U16.31(TXCLK_IN)
LVDS_R_FB: R204.1 U16.17(R_FB)
MAIN_PWR_EN: R122.1 ; also on sheet 12
mPCIE0_LED1: P16.42(LED_WWAN#) TP1.1
mPCIE0_LED2: P16.44(LED_WLAN#) TP2.1
mPCIE0_LED3: P16.46(LED_WPAN#) TP3.1
mPCIE1_LED1: P20.42(LED_WWAN#) TP4.1
mPCIE1_LED2: P20.44(LED_WLAN#) TP6.1
mPCIE1_LED3: P20.46(LED_WPAN#) TP5.1
mPCIE_PER_N0: P16.23(PER_N0) RN26.6(RC2)
mPCIE_PER_P0: P16.25(PER_P0) RN26.5(RD2)
mPCIE_PET_N0: P16.31(PET_N0) RN26.8(RA2)
mPCIE_PET_P0: P16.33(PET_P0) RN26.7(RB2)
mPCIE_USB_DN: P16.36(USB_D-) ; also on sheet 5
mPCIE_USB_DP: P16.38(USB_D+) ; also on sheet 5
mSATA_RXN: U19.25(C2+) U19.31(C1-)
mSATA_RXP: U19.24(C2-) U19.32(C1+)
mSATA_TXN: U19.22(C3-) U19.33(C0-)
mSATA_TXP: U19.23(C3+) U19.34(C0+)
P1-21_SATA_TXP: RN30.1(RA1) ; also on sheet 10 13
P1-23_SATA_TXN: RN30.2(RB1) ; also on sheet 10 13
P1-27_SATA_RXP: RN30.3(RC1) ; also on sheet 10 13
P1-29_SATA_RXN: RN30.4(RD1) ; also on sheet 10 13
P1-66_RTOUCH_XP: P10.37 ; also on sheet 5 10
P1-68_RTOUCH_XN: P10.39 ; also on sheet 5 10
P1-70_RTOUCH_YP: P10.40 ; also on sheet 5 10
P1-72_RTOUCH_YN: P10.38 ; also on sheet 5 10
P1-73_PWM: U12.J6(A14) ; also on sheet 10
P1-74_PDISP_DATA22: U12.F6(A8) ; also on sheet 10
P1-76_PDISP_DATA23: U12.F5(A9) ; also on sheet 10
P1-92_PDISP_DATA17: U12.C6(A3) ; also on sheet 10
P1-94_PDISP_DATA16: U12.C5(A2) ; also on sheet 10
P1-98_PDISP_PCLK: U12.G6(A10) ; also on sheet 10
P1-100_PDISP_HSYNC: U12.H5(A13) ; also on sheet 10
P1-102_PDISP_VSYNC: U12.H6(A12) ; also on sheet 10
P1-104_PDISP_DE: U12.G5(A11) ; also on sheet 10
P1-106_PDISP_DATA00: U11.B5(A0) ; also on sheet 10
P1-108_PDISP_DATA01: U11.B6(A1) ; also on sheet 10
P1-110_PDISP_DATA02: U11.C5(A2) ; also on sheet 10
P1-112_PDISP_DATA03: U11.C6(A3) ; also on sheet 10
P1-116_PDISP_DATA04: U11.D5(A4) ; also on sheet 10
P1-118_PDISP_DATA05: U11.D6(A5) ; also on sheet 10
P1-119_PCIE_REFCLKP: R94.1 ; also on sheet 10 12
P1-120_PDISP_DATA06: U11.E5(A6) ; also on sheet 10
P1-121_PCIE_REFCLKN: R93.1 ; also on sheet 10 12
P1-122_PDISP_DATA07: U11.E6(A7) ; also on sheet 10
P1-124_PDISP_DATA08: U11.F6(A8) ; also on sheet 10 14
P1-125_PCIE_TXP: RN26.2(RB1) ; also on sheet 10 12
P1-126_PDISP_DATA09: U11.F5(A9) ; also on sheet 10 14
P1-127_PCIE_TXN: RN26.1(RA1) ; also on sheet 10 12
P1-128_PDISP_DATA10: U11.G6(A10) ; also on sheet 10 14
P1-130_PDISP_DATA11: U11.G5(A11) ; also on sheet 10 14
P1-131_PCIE_RXP: RN26.4(RD1) ; also on sheet 10 12
P1-133_PCIE_RXN: RN26.3(RC1) ; also on sheet 10 12
P1-134_PDISP_DATA12: U11.H6(A12) ; also on sheet 10
P1-136_PDISP_DATA13: U11.H5(A13) ; also on sheet 10
P1-138_PDISP_DATA14: U11.J6(A14) ; also on sheet 10
P1-140_PDISP_DATA15: R83.2 ; also on sheet 10
P1-142_PDISP_DATA18: U12.D5(A4) ; also on sheet 10
P1-144_PDISP_DATA19: U12.D6(A5) ; also on sheet 10
P1-146_PDISP_DATA20: U12.E5(A6) ; also on sheet 10
P1-148_PDISP_DATA21: U12.E6(A7) ; also on sheet 10
P1-152_GPIO1: R62.1 ; also on sheet 5 10
P1-183_BKBAT: E8.2 ; also on sheet 10
P1-194_GPIO6: R132.2 U36.4(OUT) ; also on sheet 5 10
P20LED_AN: DS7.ANODE R215.2
PCIE0_nPERST_3V3: P16.22(PERST#) R37.1 ; also on sheet 6 12
PCIE0_REFCLKN: P16.11(REFCLK-) R93.2 ; also on sheet 12
PCIE0_REFCLKP: P16.13(REFCLK+) R94.2 ; also on sheet 12
PCIE1_nPERST_3V3: P20.22(PERST#) R40.1 ; also on sheet 6 12
PDISP_DATA15: R83.1 U11.J5(A15)
PER3P3_FB: R52.1 R53.2
PMIDI: C110.2 U25.20(PMIDI)
PMIDU: C112.2 R61.1 U25.23(PMIDU) ; also on sheet 11
RGB24_B0_3V3: P10.21 U11.B2(B0) U15.63(PD0) U16.15(TXIN15_B0)
RGB24_B1_3V3: P10.22 U11.B1 U15.62(PD1) U16.19(TXIN18_B1)
RGB24_B2_3V3: P10.23 U11.C2(B2) U15.61(PD2) U16.20(TXIN19_B2)
RGB24_B3_3V3: P10.24 U11.C1(B3) U15.60(PD3) U16.22(TXIN20_B3)
RGB24_B4_3V3: P10.25 U11.D2(B4) U15.59(PD4) U16.23(TXIN21_B4)
RGB24_B5_3V3: P10.26 U11.D1(B5) U15.58(PD5) U16.24(TXIN22_B5)
RGB24_B6_3V3: P10.27 U11.E2(B6) U15.55(PD6) U16.16(TXIN16_B6)
RGB24_B7_3V3: P10.28 U11.E1(B7) U15.54(PD7) U16.18(TXIN17_B7)
RGB24_DE_3V3: P10.34 U12.G2(B11) U15.2(DE) U16.30(TXIN26_EN)
RGB24_G0_3V3: P10.13 U11.F1(B8) U15.53(PD8) U16.4(TXIN7_G0)
RGB24_G1_3V3: P10.14 U11.F2(B9) U15.52(PD9) U16.6(TXIN8_G1)
RGB24_G2_3V3: P10.15 U11.G1(B10) U15.51(PD10) U16.7(TXIN9_G2)
RGB24_G3_3V3: P10.16 U11.G2(B11) U15.50(PD11) U16.11(TXIN12_G3)
RGB24_G4_3V3: P10.17 U11.H1(B12) U15.47(PD12) U16.12(TXIN13_G4)
RGB24_G5_3V3: P10.18 U11.H2(B13) U15.46(PD13) U16.14(TXIN14_G5)
RGB24_G6_3V3: P10.19 U11.J1(B14) U15.45(PD14) U16.8(TXIN10_G6)
RGB24_G7_3V3: P10.20 U11.J2(B15) U15.44(PD15) U16.10(TXIN11_G7)
RGB24_HSYNC_3V3: P10.32 U12.H2(B13) U15.4(HSYNC) U16.27(TXIN24_HSYNC)
RGB24_PCLK_3V3: RN8.1(RA1) RN8.2(RB1) RN8.3(RC1) U12.G1(B10)
RGB24_R0_3V3: P10.5 U12.C2(B2) U15.43(PD16) U16.51(TXIN0_R0)
RGB24_R1_3V3: P10.6 U12.C1(B3) U15.42(PD17) U16.52(TXIN1_R1)
RGB24_R2_3V3: P10.7 U12.D2(B4) U15.41(PD18) U16.54(TXIN2_R2)
RGB24_R3_3V3: P10.8 U12.D1(B5) U15.40(PD19) U16.55(TXIN3_R3)
RGB24_R4_3V3: P10.9 U12.E2(B6) U15.39(PD20) U16.56(TXIN4_R4)
RGB24_R5_3V3: P10.10 U12.E1(B7) U15.38(PD21) U16.3(TXIN6_R5)
RGB24_R6_3V3: P10.11 U12.F1(B8) U15.37(PD22) U16.50(TXIN27_R6)
RGB24_R7_3V3: P10.12 U12.F2(B9) U15.36(PD23) U16.2(TXIN5_R7)
RGB24_VSYNC_3V3: P10.33 U12.H1(B12) U15.5(VSYNC) U16.28(TXIN25_VSYNC)
RGB_LVDS_CLKN: U16.40(TXCLKOUT-) ; also on sheet 3
RGB_LVDS_CLKP: U16.39(TXCLKOUT+) ; also on sheet 3
RGB_LVDS_N0: U16.48(TXOUT0-) ; also on sheet 3
RGB_LVDS_N1: U16.46(TXOUT1-) ; also on sheet 3
RGB_LVDS_N2: U16.42(TXOUT2-) ; also on sheet 3
RGB_LVDS_N3: U16.38(TXOUT3-) ; also on sheet 3
RGB_LVDS_P0: U16.47(TXOUT0+) ; also on sheet 3
RGB_LVDS_P1: U16.45(TXOUT1+) ; also on sheet 3
RGB_LVDS_P2: U16.41(TXOUT2+) ; also on sheet 3
RGB_LVDS_P3: U16.37(TXOUT3+) ; also on sheet 3
SATA_DASDSS: P12.18(DAS/DSS) R207.1 TP7.1
SATA_RXN: RN30.5(RD2) U19.7(A1-)
SATA_RXP: RN30.6(RC2) U19.6(A1+)
SATA_TXN: RN30.7(RB2) U19.3(A0-)
SATA_TXP: RN30.8(RA2) U19.2(A0+)
STD_SATA_RXN: P12.5(RXN) U19.35(B1-)
STD_SATA_RXP: P12.6(RXP) U19.36(B1+)
STD_SATA_TXN: P12.3(TXN) U19.37(B0-)
STD_SATA_TXP: P12.2(TXP) U19.38(B0+)
SWBAT: L14.1 U21.B1(SW) U21.B2(SW)
V_RTC: D9.CATHODE E8.3 R85.1
VCOIN: BH1.2(PLUS) BT1.1(POS) D8.CATHODE D9.ANODE R85.2
VDC_IN: C87.1 C88.1 C89.1 FB6.2 FB7.2 R43.1 S5.2 U20.2(Vin) ; also on sheet 12
VPERSRC_SW: L15.1 U23.13(LX) U23.14(LX) U23.15(LX)
VRTCBAT_CHRG: D8.ANODE R49.1
VSB_1V5: C135.1 C155.1 C156.1 C158.1 C159.1 C160.1 C161.1 C162.1 C170.1 C171.1 C172.1 C173.1 C174.1 C175.1 C176.1 P16.6(+1.5V_1) P16.28(+1.5V_2) P16.48(+1.5V_3) P20.6(+1.5V_1) P20.28(+1.5V_2) P20.48(+1.5V_3) R168.2 U26.7(Vout1) U26.8(Vout2)
VSB_3V3: C46.1 C47.1 C50.1 C51.1 C52.1 C53.1 C54.1 C55.2 C56.2 C57.2 C58.2 C59.2 C60.2 C61.2 C64.1 C65.1 C66.1 C67.1 C68.1 C69.1 C70.1 C71.1 C72.1 C77.1 C78.1 C85.1 C106.1 C107.1 C120.1 C121.1 C122.1 C134.1 C138.1 C139.1 C140.1 C142.1 C143.1 C144.1 C145.1 C146.1 C147.1 C148.1 C149.1 C154.1 C163.1 C164.1 C165.1 C166.1 C167.1 C168.1 C169.1 C199.1 C228.1 C229.1 L8.1 L16.2 P10.4 P12.8(V33) P12.9(V33) P12.10(V33/PC) P16.2(+3.3V_1) P16.24(+3.3V_AUX) P16.39(RSVD6) P16.41(RSVD7) P16.52(+3.3V_2) P20.2(+3.3V_1) P20.24(+3.3V_AUX) P20.39(RSVD6) P20.41(RSVD7) P20.52(+3.3V_2) R27.2 R28.2 R29.2 R37.2 R40.2 R49.2 R50.1 R77.1 R127.1 R156.1 R157.1 R158.1 R204.2 R205.1 R215.1 RN11.5(RD2) RN11.7(RB2) RN11.8(RA2) RN12.1(RA1) RN12.2(RB1) RN13.3(RC1) RN14.8(RA2) U11.C3(VCCB) U11.H3(VCCB) U12.C3(VCCB) U12.H3(VCCB) U14.5(VIN) U15.1(DVDD) U15.3(VREF) U15.12(DVDD) U15.18(PVDD) U15.23(TVDD) U15.29(TVDD) U15.33(DVDD) U15.49(N~{C}AVDD) U16.1(VCC) U16.9(VCC) U16.26(VCC) U16.34(PLL_VCC) U16.44(LVDS_VCC) U19.5(VDD) U19.8(VDD) U19.13(VDD) U19.18(VDD) U19.20(VDD) U19.30(VDD) U19.40(VDD) U19.42(VDD) U36.5(VCC) ; also on sheet 1 3 5 6 10 12
VSB_3V3_FB: R50.2 R54.2 U22.4(FB)
VSB_PER: C108.1 C109.1 C123.1 C124.1 C125.1 C126.1 C127.1 C128.1 L15.2 Q9.2(G1) Q9.5(G2) R41.2 R51.1 R52.2 R132.1 RN10.7(RB2) RN10.8(RA2) U11.A1(T/~{R}1) U11.C4(VCCA) U11.H4(VCCA) U11.K1(T/~{R}2) U12.A1(T/~{R}1) U12.C4(VCCA) U12.H4(VCCA) U12.K1(T/~{R}2) ; also on sheet 1 3 5 6 10 14
VSB_PER_FB: R51.2 R53.1 R55.2 U23.4(FB)
WLD_CAT: P10.1 R23.1 R25.1
WLD_OUT: D2.CATHODE D3.1(CATHODE) P10.2
WLD_RES: R24.1 R25.2
WLD_SW: D2.ANODE L8.2 U14.1(SW)

Not connected (* = marked no-connect by the designer): J5 13(CE_Remote)* 14(NC)*; P10 35*; P16 1(WAKE#)* 3(RSVD1)* 5(RSVD2)* 7(CLKREQ#)* 8(RSVD13)* 10(RSVD14)* 12(RSVD15)* 14(RSVD16)* 16(RSVD17)* 17(RSVD3)* 19(RSVD4)* 20(RSVD18)* 43(RSVD8)* 45(RSVD9)* 47(RSVD10)* 49(RSVD11)* 51(RSVD12)*; P20 1(WAKE#)* 3(RSVD1)* 5(RSVD2)* 7(CLKREQ#)* 8(RSVD13)* 10(RSVD14)* 12(RSVD15)* 14(RSVD16)* 16(RSVD17)* 17(RSVD3)* 19(RSVD4)* 20(RSVD18)* 45(RSVD9)* 47(RSVD10)* 49(RSVD11)* 51(RSVD12)*; RN8 4(RD1)* 5(RD2)*; RN12 8(RA2)*; RN13 5(RD2)*; RN14 4(RD1)* 5(RD2)*; U11 A2(NC)* A3(NC)* A4(NC)* A5(NC)* K2(NC)* K3(NC)* K4(NC)* K5(NC)*; U12 A2(NC)* A3(NC)* A4(NC)* A5(NC)* B1* B2(B0)* B5(A0)* B6(A1)* J2(B15)* J5(A15)* K2(NC)* K3(NC)* K4(NC)* K5(NC)*; U17 3(IO2)*; U22 6(NC)* 8(NC)* 16(NC)*; U23 6(NC)* 8(NC)* 16(NC)*; U24 1(AIN1)* 2(AIN0)* 8(VOUT)*; U25 1(NC)*; U26 3(PGOOD)*; U31 3(PGOOD)*; U32 3(PGOOD)*

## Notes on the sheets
sheet 7
- SHIFT PARALLEL
  RGB TO 3.3V
- PARALLEL
  RGB LCD
  & TOUCH
- SHENZHEN STARTEK
  ELECTRONIC TECHNOLOGY
  KD050C-1A-TP LCD
- PARALLEL RGB to LVDS
- Place on
  board bottom
- NOTE: In case CoM/SoM I/O is @ 3.3V
  levels, such as (CM-T43) level shifting is
  not required. We use level shifting here
  only to be compatible with  non-3.3V I/O
  CoMs (such as CM-T54 or CM-QS600)
- DO NOT
  POPULATE
  FOR:
  SB-SOM-QS600
- Make sure DATA to
  COLOR mapping is valid
  for all CoMs compatible
  with SB-SOM
- KD050C-1A-TP
- XR
- XL
- YD
- YU
- Typical LED configuration 6 serially connected LED's
- 3.6V typical Vf x 6 = 21.6V 15-20mA
- DNP
- DNP
- DNP
- DNP
- PARALLEL RGB-to-DVI
- Circuitry is designed to shift
  DDC signals logic levels between
  VSB_PER (1.8 or 3.3V) and 5V.
- DNP
- DO NOT
  POPULATE
  FOR:
  SB-SOM-QS600
- STRAPS:
   Without I2C:
     1. Monitor detection through MSEN
     2. 24bit input mode
     3. RGB data latched on rising PCLK edge
     4. De-skewing is set to 0b001 (-0.9nS <-> -0.75 nS)
   With I2C: Full SW control
- DNP
- 7-bit I2C address:
  0b011,1000
- DNP
- DNP
- Assemble for NON I2C config
- DNP
- Assemble for I2C config
sheet 8
- PRIMARY mini-PCIE
- DO NOT
  POPULATE
  FOR:
  SB-SOM-T43
  SB-SOM-T54
- STANDARD SATA
  CONNECTOR
- PCIE/SATA/mSATA MUX
- DO NOT
  POPULATE
  FOR:
  SB-SOM-T43
- SEL = HIGH
      PortA <=> PortC
  SEL = LOW
      PortA <=> PortB
- DNP
- SATA drives requiring 12V supply
  voltage are not supported by default.
  Assemble the ferrite to support
  such drives. Note: VDC_IN rail
   must be @ 12V to support this
- JUMPER POPULATED (Forced Mode):
      P20 is used for PCI-Express interface
      P12 is used for SATA interface
  JUMPER REMOVED (Automatic mode):
      Daughter card type in P20 selects mux mode:
          P20 Empty or with mSATA daughter card:
                  Sata routed to P20
                  2nd PCI-E unused.
          P20 with mPCI-E daughtercard:
                  Sata routed to P12
                  2nd PCI-E routed to P20
- SECONDARY PCIE/mSATA/USB
- Pin 43 shall be floating onboard
  all mSATA drives while
  grounded on all
  mini-PCI-Express daughter
  cards. This allows pin 43 to
  control U19 sel signal
sheet 9
- DC INPUT
- DC-to-5.25V
- Vout=Vfb*(1+Rt/Rb)=0.92*(1+47/10)=5.244V.
  Note: in case VDC_IN is @ minimum voltage (5.3V),
   BQ_INSRC(max) is @ 5.3*0.8 = 4.24V,  (still valid for  BQ24161 input)
- DNP
- BOOST_5V SOURCE
- VIN_DC(min) = 5.3V
  VIN_DC(max) = 16V
- POPULATE ONLY
  FOR "T54" or "T43" OPTION
- DNP
- DNP
- DNP
- POWER JACK not inserted:
  DC_IN_DET = low
  POWER JACK inserted:
  DC_IN_DET = High-Z
- POPULATE ONLY
  FOR "ATP" OPTION
- DNP
- VSB_3V3
  SOURCE
- VSB_PER
  SOURCE
- RTC BATTERY
- RTC function:
   Enable: Short pins 2 <-> 3
   Disable:
    CM-T54/CM-T43: Short pins 2 <-> 1
    CM-QS600: Open
- DNP
- Source of the onboard 3.3V power rail
  used for most onboard integrated
  circuitry
- Vout=Vfb*(1+Rt/Rb)=0.6*(1+100/22.1)=3.315V.
- Source of the onboard VPER power rail used for
  most onboard peripherails interfaced directly with
  CoM I/O signals.
  1. VPER rail is 3.3V when CoM/SoM I/O is  @ 3.3V
  (such as CM-T43)
  2. VPER rail is 1.8V when CoM/SoM I/O is  @ 1.8V
  (such as CM-T54 and CM-QS600)
- Vout=Vfb*(1+Rt/Rb)=0.6*(1+100/22.1)=3.315V.
- Vout=Vfb*(1+Rt/Rb)=0.6*(1+(100*76.8/176.8)/22.1)=1.779V.
- DNP
- R53 populated ==> VSB_PER=1.8V
  R53 not populated ==> VSB_PER=3.3V
- Backup Battery Charger
  Available with:
    CM-QS600
    CM-T54
  Not Available with:
    CM-T43
- DNP
- DO NOT
  POPULATE
  FOR:
  SB-SOM-T43
- DNP
- 1V5
  SOURCE
- Li-Po Battery Connector &
  Charging supervisor
- POWER PROVISIONS
- NOT POPULATED BY DEFAULT
- Vout=Vfb*(1+Rt/Rb)=0.8*(1+9.1/10)=1.528V
- 7-bit I2C address:
  0b011,0110
- These placeholders allow generating additional
  voltages rails often required by different camera sensors.
  The VCC_AUX1 & VCC_AUX2 voltages can be sourced into the sensor from the 100mil camera header
  VCC_AUX1 & VCC_AUX2 voltage can be changed by changing the resistance of R169, R155, R170 & R162
- VCC_AUX1 source
- Vout=Vfb*(1+Rt/Rb)=0.8*(1+9.1/10)=1.528V
- PRIMARY POWER SOURCE & BATTERY CHARGER
- DNP
- VCC_AUX2 source
- Vout=Vfb*(1+Rt/Rb)=0.8*(1+9.1/10)=1.528V
- DNP
- BQ24161 minimum output
   voltage @ VCC_CM = 3.4V
- DNP
- Assuming NTC properties
- BQ24161 USB input initial current limit
  is set by PSEL pin value
  PSEL = 1 ==> limit is 100mA
  PSEL = 0 ==> limit is 1500mA
- NTC resiststance
- 10K
- Battery temperature
- 25degC
- 6K
- 40degC
- 7-bit I2C address:
  0b110,1011
- 25K
- 0degC
- DO NOT
  POPULATE
  FOR:
  SB-SOM-T54
- DO NOT
  POPULATE
  FOR:
  SB-SOM-QS600
- CHARGER LED
